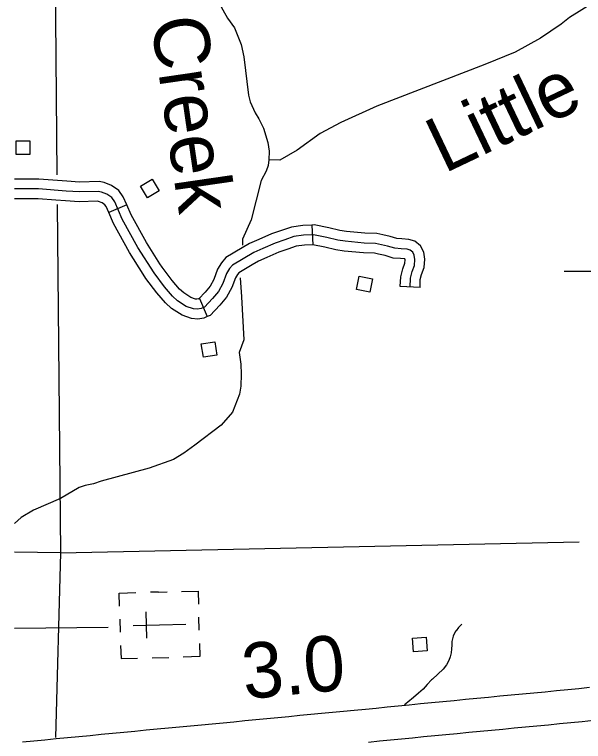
# Model space of a CAD drawing. Extents: x 1370130 to 1380143, y 377636 to 380256.
# Drawn here: x 1376950.4 to 1377071.7, y 379289.3 to 379444.4 of the extents above; entities that cross this region are included whole.
import ezdxf

# ---------------------------------------------------------------- set-up
doc = ezdxf.new("R2010")
doc.units = 0
for name, color, linetype in [('Level 15', 7, 'Continuous'), ('Level 35', 7, 'Continuous'), ('Level 45', 7, 'Continuous'), ('Level 48', 7, 'Continuous'), ('Level 5', 7, 'Continuous'), ('Level 56', 7, 'Continuous'), ('Level 57', 7, 'Continuous'), ('R_Draft', 7, 'Continuous')]:
    doc.layers.add(name, color=color, linetype=linetype)

msp = doc.modelspace()

# ---------------------------------------------------------------- linework, layer by layer
at = {"layer": 'Level 15'}
for p, q in [((1377063.54, 379299.88), (1377061.12, 379299.64)), ((1377065.95, 379300.12), (1377063.54, 379299.88)), ((1377068.35, 379300.35), (1377065.95, 379300.12)), ((1377070.71, 379300.59), (1377068.35, 379300.35)), ((1377073.03, 379300.83), (1377070.71, 379300.59)), ((1377046.57, 379298.27), (1377044.13, 379298.04)), ((1377049, 379298.5), (1377046.57, 379298.27)), ((1377051.42, 379298.74), (1377049, 379298.5)), ((1377053.85, 379298.97), (1377051.42, 379298.74)), ((1377056.28, 379299.19), (1377053.85, 379298.97)), ((1377058.69, 379299.42), (1377056.28, 379299.19)), ((1377061.12, 379299.64), (1377058.69, 379299.42)), ((1377029.87, 379296.64), (1377027.53, 379296.4)), ((1377032.21, 379296.87), (1377029.87, 379296.64)), ((1377034.55, 379297.11), (1377032.21, 379296.87)), ((1377036.92, 379297.34), (1377034.55, 379297.11)), ((1377039.31, 379297.57), (1377036.92, 379297.34)), ((1377041.71, 379297.81), (1377039.31, 379297.57)), ((1377044.13, 379298.04), (1377041.71, 379297.81)), ((1377013.53, 379295.08), (1377011.19, 379294.85)), ((1377015.85, 379295.3), (1377013.53, 379295.08)), ((1377018.17, 379295.51), (1377015.85, 379295.3)), ((1377020.5, 379295.73), (1377018.17, 379295.51)), ((1377022.84, 379295.95), (1377020.5, 379295.73)), ((1377025.19, 379296.17), (1377022.84, 379295.95)), ((1377027.53, 379296.4), (1377025.19, 379296.17)), ((1376997.17, 379293.49), (1376994.86, 379293.26)), ((1376999.49, 379293.72), (1376997.17, 379293.49)), ((1377001.83, 379293.95), (1376999.49, 379293.72)), ((1377004.16, 379294.16), (1377001.83, 379293.95)), ((1377006.5, 379294.38), (1377004.16, 379294.16)), ((1377008.84, 379294.61), (1377006.5, 379294.38)), ((1377011.19, 379294.85), (1377008.84, 379294.61)), ((1377069.04, 379293.38), (1377071.43, 379293.62)), ((1377071.43, 379293.62), (1377073.84, 379293.88)), ((1376980.81, 379291.95), (1376978.43, 379291.72)), ((1376983.19, 379292.18), (1376980.81, 379291.95)), ((1376985.56, 379292.4), (1376983.19, 379292.18)), ((1376987.91, 379292.61), (1376985.56, 379292.4)), ((1376990.24, 379292.83), (1376987.91, 379292.61)), ((1376992.55, 379293.04), (1376990.24, 379292.83)), ((1376994.86, 379293.26), (1376992.55, 379293.04)), ((1377052.1, 379291.77), (1377054.51, 379292)), ((1377054.51, 379292), (1377056.92, 379292.22)), ((1377056.92, 379292.22), (1377059.34, 379292.45)), ((1377059.34, 379292.45), (1377061.78, 379292.68)), ((1377061.78, 379292.68), (1377064.22, 379292.91)), ((1377064.22, 379292.91), (1377066.63, 379293.15)), ((1377066.63, 379293.15), (1377069.04, 379293.38)), ((1376966.47, 379290.57), (1376964.07, 379290.34)), ((1376968.87, 379290.8), (1376966.47, 379290.57)), ((1376971.27, 379291.03), (1376968.87, 379290.8)), ((1376973.66, 379291.26), (1376971.27, 379291.03)), ((1376976.05, 379291.49), (1376973.66, 379291.26)), ((1376978.43, 379291.72), (1376976.05, 379291.49)), ((1377035.25, 379290.14), (1377037.6, 379290.38)), ((1377037.6, 379290.38), (1377039.98, 379290.61)), ((1377039.98, 379290.61), (1377042.38, 379290.84)), ((1377042.38, 379290.84), (1377044.8, 379291.07)), ((1377044.8, 379291.07), (1377047.23, 379291.3)), ((1377047.23, 379291.3), (1377049.67, 379291.53)), ((1377049.67, 379291.53), (1377052.1, 379291.77)), ((1376954.47, 379289.4), (1376952.09, 379289.17)), ((1376956.87, 379289.64), (1376954.47, 379289.4)), ((1376959.27, 379289.87), (1376956.87, 379289.64)), ((1376961.67, 379290.11), (1376959.27, 379289.87)), ((1376964.07, 379290.34), (1376961.67, 379290.11)), ((1377025.87, 379289.21), (1377028.22, 379289.44)), ((1377028.22, 379289.44), (1377030.57, 379289.67)), ((1377030.57, 379289.67), (1377032.91, 379289.91)), ((1377032.91, 379289.91), (1377035.25, 379290.14))]:
    msp.add_line(p, q, dxfattribs=at)
at = {"layer": 'Level 35'}
for points in [[(1376992.05, 379451), (1376992.69, 379449.39), (1376994.82, 379445.41), (1376995.77, 379443.68), (1376997.25, 379441.57), (1376998.74, 379438.06), (1376999.31, 379435.39), (1377000.3, 379427.22), (1377000.61, 379425.77), (1377001.7, 379423.43), (1377002.5, 379422.19), (1377003.46, 379420.15), (1377004.41, 379417.16), (1377004.67, 379415.29), (1377004.63, 379413.41), (1377004.45, 379412.2), (1377004.01, 379410.98), (1377002.99, 379409.04), (1377000.86, 379400.61), (1376999.02, 379396.53), (1376998.99, 379395.22)], [(1377074.58, 379447.4), (1377068.7, 379443.8), (1377066.94, 379442.39), (1377062.54, 379439.37)], [(1377062.54, 379439.37), (1377057.17, 379436.43), (1377050.67, 379433.73), (1377027.67, 379424.89), (1377019.97, 379421.36), (1377015.55, 379419.07), (1377010.67, 379415.51), (1377006.98, 379413.33), (1377004.63, 379413.41)], [(1376998.46, 379388.25), (1376998.81, 379384.22), (1376999.26, 379374.99), (1376998.27, 379372.35), (1376998.61, 379369.84), (1376998.74, 379367.71), (1376998.61, 379365.13), (1376998.33, 379363.44), (1376996.85, 379359.57), (1376994.41, 379356.82), (1376988.8, 379352.53), (1376986.48, 379350.87), (1376984.27, 379349.53), (1376979.08, 379347.67), (1376968.84, 379344.89), (1376967.23, 379344.3), (1376965.43, 379343.95), (1376964.16, 379343.49), (1376960.16, 379341.21), (1376954.41, 379338.68), (1376951.81, 379337.1), (1376950.37, 379335.83)], [(1377045.8, 379314.38), (1377045.04, 379313.63), (1377044.53, 379312.97), (1377044.45, 379312.85), (1377043.89, 379311.77), (1377043.67, 379310.64), (1377043.65, 379310.5), (1377043.64, 379309.85), (1377043.58, 379309.1), (1377043.49, 379308.22), (1377043.29, 379307.38), (1377043.01, 379306.58), (1377042.53, 379305.7), (1377041.8, 379304.75), (1377039.52, 379302.64), (1377039.33, 379302.46), (1377038.38, 379301.48), (1377037.51, 379300.53), (1377036.56, 379299.63), (1377035.47, 379298.73), (1377034.27, 379297.71), (1377033.54, 379297.13)]]:
    msp.add_lwpolyline(points, dxfattribs=at)
at = {"layer": 'Level 45'}
for p, q in [((1376974.3, 379403.84), (1376970.45, 379402.17)), ((1377013.76, 379399.51), (1377013.97, 379395.31)), ((1377036.85, 379386.22), (1377032.65, 379386.37)), ((1376989.85, 379383.84), (1376991.48, 379379.97))]:
    msp.add_line(p, q, dxfattribs=at)
for points in [[(1376959.52, 379409.01), (1376955.57, 379409.33), (1376950.37, 379409.33)], [(1376974.3, 379403.84), (1376973.57, 379405.53), (1376972.6, 379406.88), (1376971.05, 379407.96), (1376969.5, 379408.57), (1376968.42, 379408.8), (1376964.25, 379408.69), (1376961.51, 379408.85), (1376959.52, 379409.01)], [(1377034.75, 379386.29), (1377034.82, 379388.18), (1377035.17, 379389.58), (1377035.66, 379390.91), (1377035.76, 379392.17), (1377035.62, 379393.08), (1377035.31, 379393.71), (1377034.72, 379394.17), (1377034.09, 379394.38), (1377032.86, 379394.45), (1377031.5, 379394.55), (1377029.92, 379395.04), (1377027.37, 379395.6), (1377024.94, 379395.67), (1377020.9, 379396.06), (1377019.33, 379396.3), (1377016.98, 379396.86), (1377014.12, 379397.42), (1377012.02, 379397.32), (1377009.92, 379397.04), (1377008, 379396.37), (1377005.97, 379395.67), (1377003.31, 379394.52), (1377001.42, 379393.68), (1376996.84, 379390.95), (1376996.21, 379390.21), (1376995.58, 379389.2), (1376994.81, 379387.03), (1376993.87, 379385.32), (1376992.61, 379383.81), (1376990.86, 379381.99), (1376990.2, 379381.71), (1376989.36, 379381.57), (1376988.55, 379381.64), (1376987.01, 379382.17), (1376985.15, 379383.37), (1376984.08, 379384.37), (1376982.36, 379386.36), (1376980.12, 379389.3), (1376976.7, 379394.73), (1376973.34, 379400.78), (1376971.73, 379404.49), (1376971.1, 379405.37), (1376970.05, 379406.1), (1376968.9, 379406.56), (1376968.23, 379406.7), (1376964.21, 379406.59), (1376961.37, 379406.76), (1376955.49, 379407.23), (1376950.37, 379407.23)], [(1376959.19, 379404.83), (1376955.4, 379405.13), (1376950.37, 379405.13)], [(1376970.45, 379402.17), (1376969.89, 379403.45), (1376969.6, 379403.85), (1376969.05, 379404.24), (1376968.29, 379404.54), (1376968.04, 379404.59), (1376964.18, 379404.49), (1376961.22, 379404.66), (1376959.19, 379404.83)], [(1376981.37, 379391.26), (1376978.5, 379395.8), (1376975.23, 379401.71), (1376974.3, 379403.84)], [(1376977.82, 379389.01), (1376974.89, 379393.66), (1376971.45, 379399.85), (1376970.45, 379402.17)], [(1377013.76, 379399.51), (1377011.83, 379399.41), (1377009.43, 379399.09), (1377007.31, 379398.36), (1377005.21, 379397.63), (1377002.47, 379396.44), (1377000.45, 379395.55), (1376998.91, 379394.63)], [(1377028.92, 379397.41), (1377027.63, 379397.7), (1377025.07, 379397.77), (1377021.16, 379398.14), (1377019.73, 379398.36), (1377017.43, 379398.92), (1377014.27, 379399.53), (1377013.76, 379399.51)], [(1377036.85, 379386.22), (1377036.91, 379387.89), (1377037.18, 379388.97), (1377037.73, 379390.46), (1377037.88, 379392.25), (1377037.65, 379393.73), (1377036.97, 379395.09), (1377035.71, 379396.05), (1377034.49, 379396.46), (1377033, 379396.54), (1377031.9, 379396.63), (1377030.46, 379397.07), (1377028.92, 379397.41)], [(1376998.91, 379394.63), (1376995.47, 379392.58), (1376994.51, 379391.46), (1376993.68, 379390.11), (1376992.89, 379387.89), (1376992.13, 379386.51), (1376991.04, 379385.21), (1376989.65, 379383.76), (1376989.85, 379383.84)], [(1377013.97, 379395.31), (1377012.21, 379395.22), (1377010.41, 379394.98), (1377008.68, 379394.39), (1377006.73, 379393.71), (1377004.16, 379392.6), (1377002.39, 379391.81), (1377001.06, 379391.02)], [(1377028.02, 379393.31), (1377027.11, 379393.51), (1377024.81, 379393.57), (1377020.64, 379393.97), (1377018.92, 379394.24), (1377016.54, 379394.81), (1377013.97, 379395.31), (1377013.97, 379395.31)], [(1377032.65, 379386.37), (1377032.73, 379388.48), (1377033.16, 379390.2), (1377033.59, 379391.37), (1377033.65, 379392.1), (1377033.62, 379392.3), (1377032.72, 379392.35), (1377031.1, 379392.48), (1377029.39, 379393.01), (1377028.02, 379393.31)], [(1376989.85, 379383.84), (1376989.61, 379383.74), (1376989.27, 379383.69), (1376988.99, 379383.71), (1376987.94, 379384.07), (1376986.45, 379385.03), (1376985.59, 379385.83), (1376984, 379387.69), (1376981.85, 379390.5), (1376981.37, 379391.26)], [(1377001.06, 379391.02), (1376998.21, 379389.32), (1376997.91, 379388.97), (1376997.49, 379388.28), (1376996.73, 379386.17), (1376995.61, 379384.12), (1376994.17, 379382.41), (1376992.07, 379380.22), (1376991.48, 379379.97)], [(1376991.48, 379379.97), (1376990.78, 379379.68), (1376989.44, 379379.46), (1376988.12, 379379.57), (1376986.09, 379380.26), (1376983.86, 379381.7), (1376982.56, 379382.91), (1376980.73, 379385.04), (1376978.4, 379388.1), (1376977.82, 379389.01)]]:
    msp.add_lwpolyline(points, dxfattribs=at)
at = {"layer": 'Level 5'}
for points in [[(1376958.81, 379477.15), (1376959.42, 379410.2)], [(1376959.48, 379403.93), (1376960.17, 379329.55)], [(1376960.17, 379329.55), (1377070.77, 379331.95)], [(1376960.17, 379329.55), (1376950.37, 379329.72)], [(1376960.17, 379329.55), (1376959.09, 379290.17)]]:
    msp.add_lwpolyline(points, dxfattribs=at)
at = {"layer": 'Level 56'}
for points in [[(1376950.71, 379414.57), (1376950.71, 379417.48), (1376953.63, 379417.48), (1376953.63, 379414.57)], [(1376981.24, 379406.83), (1376978.76, 379405.3), (1376977.22, 379407.79), (1376979.7, 379409.32)], [(1377026.72, 379388.07), (1377026.15, 379385.21), (1377023.29, 379385.78), (1377023.85, 379388.63)], [(1376993.1, 379374.62), (1376993.55, 379371.74), (1376990.66, 379371.3), (1376990.21, 379374.18)], [(1377038.15, 379311.62), (1377038.37, 379308.71), (1377035.46, 379308.49), (1377035.23, 379311.39)]]:
    msp.add_lwpolyline(points, close=True, dxfattribs=at)
at = {"layer": 'Level 57'}
for p, q in [((1376981.11, 379321.22), (1376979.39, 379321.18)), ((1376981.11, 379321.22), (1376982.89, 379321.27)), ((1376978.57, 379311.36), (1376978.42, 379316.98)), ((1376972.86, 379315.42), (1376972.93, 379312.63)), ((1376989.73, 379313.06), (1376989.65, 379315.86)), ((1376975.69, 379314.08), (1376986.89, 379314.37)), ((1376981.29, 379314.23), (1376981.29, 379314.23)), ((1376981.29, 379314.23), (1376981.29, 379314.23)), ((1376979.75, 379307.18), (1376983.25, 379307.28))]:
    msp.add_line(p, q, dxfattribs=at)
for points in [[(1376986.01, 379321.35), (1376989.51, 379321.44), (1376989.58, 379318.64)], [(1376972.79, 379318.21), (1376972.71, 379321.01), (1376976.21, 379321.1)], [(1376950.37, 379313.54), (1376970.35, 379313.72)], [(1376973, 379309.81), (1376973.08, 379307.01), (1376976.58, 379307.1)], [(1376989.8, 379310.25), (1376989.87, 379307.45), (1376986.37, 379307.36)]]:
    msp.add_lwpolyline(points, dxfattribs=at)
at = {"layer": 'R_Draft'}
msp.add_lwpolyline([(1377067.57, 379389.71), (1377263.22, 379389.71)], dxfattribs=at)

# ---------------------------------------------------------------- texts
at = {"layer": 'Level 35'}
for s, rotation, p in [('Creek', 278.2807, (1376979.41, 379443.36)), ('Little', 25.4621, (1377042, 379410.44))]:
    msp.add_text(s, height=11.827, rotation=rotation, dxfattribs=at).set_placement(p)
at = {"layer": 'Level 48'}
msp.add_text('3.0', height=11.827, rotation=5.535, dxfattribs=at).set_placement((1376999.45, 379298.33))

doc.saveas('drawing.dxf')
